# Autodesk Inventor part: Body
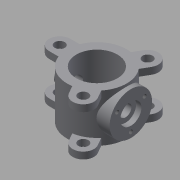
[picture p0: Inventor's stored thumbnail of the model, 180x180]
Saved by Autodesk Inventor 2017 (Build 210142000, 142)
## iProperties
Created: 2011-04
Part Number: Body
Material: Generic
Document SubType Name: Modeling
Designer: Dell
Density: 1 g/cm^3
Appearance: Default
Author: Dell
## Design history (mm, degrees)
sketch "Sketch1"
  geometry: 1 further point
sketch "Sketch2"
  geometry: C1 r 97 at (0, 0); C2 r 140 at (0, 0); 1 further point
  constraints: 2 centre point, 1 coincident
  dimensions: "d0" = 194 diameter of C1; "d1" = 280 diameter of C2
extrude "Extrusion1" new body sketch "Sketch2" stored distance "d2" = 225; taper "d3" = 0 deg
workplane "Work Plane1"
sketch "Sketch3"
  geometry: L1 (-140, 112.5)-(140, 112.5) reference; C1 r 100 at (0, 0); 1 further point
  constraints: 1 centre point, 1 coincident
  dimensions: "d5" = 200 diameter of C1; "d7" = 112.5 distance from line of point (0, 0) L1 (derived)
extrude "Extrusion2" join sketch "Sketch3" stored distance "d8" = 225; taper "d9" = 0 deg
hole "Hole1" diameter "d12" = 56; stored, may be unused: countersink angle "d16" = 90 deg, drill point angle "d18" = 118 deg; dims "d13" = 6, "d14" = 100, "d15" = 25, "d17" = 428.75, "d39" = 10, "d40" = 10
workplane "Work Plane2"
sketch "Sketch4"
  geometry: C1 r 37.5 at (0, 0); C2 r 28 at (0, 0); 1 further point
  constraints: 2 centre point, 1 coincident
  dimensions: "d20" = 75 diameter of C1; "d37" = 56 diameter of C2
sketch "Sketch5"
  geometry: L1 (130.767, -50)-(175, -50); L2 (175, 50)-(130.767, 50); C1 r 23.5 at (175, 0); A1 r 50 centre (175, 0) between (175, -50) and (175, 50); A2 r 140 centre (0, 0) between (130.767, -50) and (130.767, 50); 1 further point
  constraints: 4 end point, 4 point on circle, 3 centre point, 2 coincident
  dimensions: "d29" = 50 radius of A1 (derived); "d30" = 47 diameter of C1 (derived); "d31" = 175 distance of A1.centre point (0, 0)
extrude "Extrusion4" join sketch "Sketch5" distance "d32" = 32; taper "d33" = 0 deg
pattern_circular "Circular Pattern1" dims angle "d35" = 360 deg
mirror "Mirror1"
extrude "Extrusion5" join sketch "Sketch4" stored distance "d38" = 32; taper "d41" = 0 deg; dims "d13" = 6
sketch "Sketch6"
  geometry: C1 r 50 at (0, 0); C2 r 100 at (0, 0); 3 further points
  constraints: 2 centre point, 4 other
  dimensions: "d44" = 75 distance of point (75, 0) C1.centre; "d45" = 360 deg dimension on C1.centre point (75, 0) (derived)
hole "Hole2" sketch "Sketch6" at (-37.5, 64.952) diameter "d46" = 18.376; stored, may be unused: countersink angle "d50" = 90 deg, drill point angle "d52" = 118 deg; dims "d47" = 40, "d48" = 4, "d49" = 2, "d51" = 47.3
pattern_circular "Circular Pattern2" dims angle "d54" = 360 deg
body "Solid1"
other parameters: "d19" = -325
